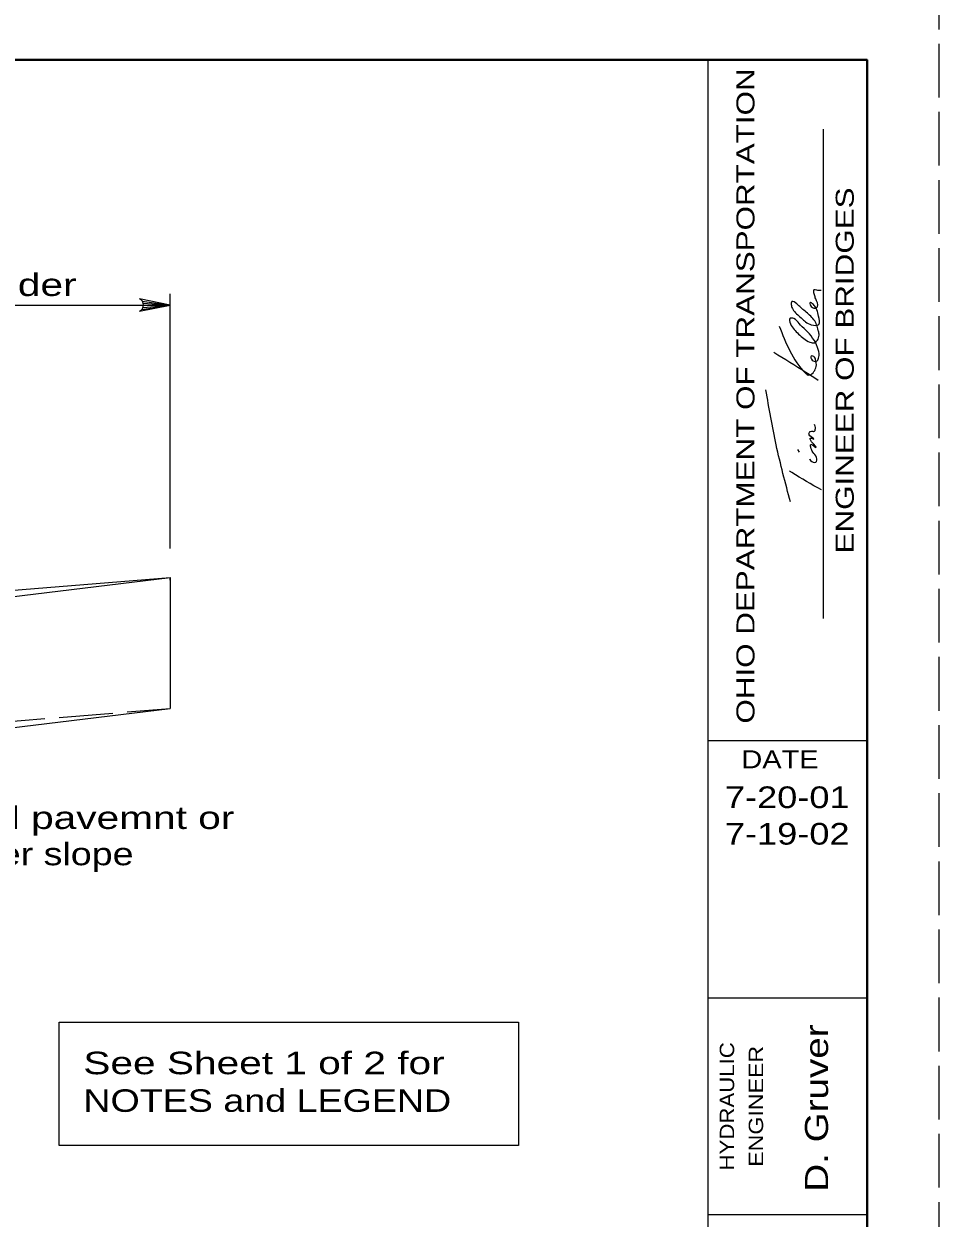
# Model space of a CAD drawing. Extents: x 758.3 to 792.3, y 849.7 to 893.7.
# Drawn here: x 785.98 to 792.32, y 863.16 to 871.44 of the extents above; entities that cross this region are included whole.
import ezdxf
from ezdxf.enums import TextEntityAlignment as Align

# ---------------------------------------------------------------- set-up
doc = ezdxf.new("R2010")
doc.units = 0
doc.header["$LTSCALE"] = 0.062
doc.linetypes.add('LONG_DASHED', pattern=[7.5, 6, -1.5])
doc.layers.add('1', color=7, linetype='Continuous', lineweight=13)

msp = doc.modelspace()

# ---------------------------------------------------------------- linework, layer by layer
at = {"layer": '1', "lineweight": 25}
for p, q in [((760.3205, 871.18817), (791.8205, 871.18817)), ((790.7205, 850.18817), (790.7205, 871.18817)), ((791.8205, 871.18817), (791.8205, 850.18817)), ((781.987, 866.99775), (786.9905, 867.60233)), ((782.38925, 867.23167), (786.9905, 867.60233)), ((786.9905, 867.60233), (786.9905, 866.69533)), ((781.987, 866.09075), (786.9905, 866.69533)), ((791.8205, 866.47233), (790.7205, 866.47233)), ((791.8205, 864.68817), (790.7205, 864.68817)), ((791.8205, 863.18817), (790.7205, 863.18817))]:
    msp.add_line(p, q, dxfattribs=at)
at = {"layer": '1'}
for p, q in [((791.51925, 867.31917), (791.51925, 870.70925)), ((786.9905, 867.80475), (786.9905, 869.56917)), ((781.987, 869.4905), (786.9905, 869.4905)), ((786.79433, 869.4605), (786.9905, 869.4905)), ((786.79667, 869.51758), (786.9905, 869.4905)), ((786.80175, 869.47308), (786.9905, 869.4905)), ((786.80317, 869.50417), (786.9905, 869.4905)), ((786.80517, 869.4905), (786.9905, 869.4905)), ((791.35175, 868.47008), (791.34158, 868.48933)), ((786.9905, 867.58433), (786.9905, 867.60233))]:
    msp.add_line(p, q, dxfattribs=at)
at = {"layer": '1', "linetype": 'LONG_DASHED', "lineweight": 25}
msp.add_line((781.987, 866.29225), (786.9905, 866.69533), dxfattribs=at)
at = {"layer": '1', "linetype": 'LONG_DASHED'}
msp.add_lwpolyline([(758.3205, 849.68817), (792.3205, 849.68817), (792.3205, 871.68817), (758.3205, 871.68817)], close=True, dxfattribs=at)
at = {"layer": '1', "lineweight": 40}
msp.add_lwpolyline([(760.3205, 871.18817), (791.8205, 871.18817), (791.8205, 850.18817), (760.3205, 850.18817)], close=True, dxfattribs=at)
at = {"layer": '1'}
msp.add_lwpolyline([(786.77633, 869.44767), (786.9905, 869.4905), (786.77633, 869.53333)], dxfattribs=at)
at = {"layer": '1', "lineweight": 25}
msp.add_lwpolyline([(786.22108, 864.52333), (789.40483, 864.52333), (789.40483, 863.66692), (786.22108, 863.66692)], close=True, dxfattribs=at)
at = {"layer": '1'}
msp.add_arc((786.75906, 869.49051), 0.04623, 292.08605, 67.91218, dxfattribs=at)
for points in [[(791.21233, 869.34517), (791.3955, 869.01683), (791.41067, 869.00625), (791.42083, 869.00625), (791.45275, 869.02992), (791.46783, 869.06408), (791.46283, 869.11533), (791.44592, 869.13717), (791.43242, 869.13717), (791.43067, 869.12417), (791.44083, 869.109), (791.45433, 869.10058), (791.46942, 869.10058), (791.48458, 869.12217), (791.488, 869.1415), (791.47775, 869.19683), (791.3955, 869.31725), (791.35, 869.36192), (791.31308, 869.3965), (791.28792, 869.39867), (791.28967, 869.36008), (791.31483, 869.32133), (791.38208, 869.259), (791.42417, 869.23358), (791.45783, 869.22908), (791.48117, 869.25508), (791.488, 869.28925), (791.48292, 869.315), (791.45275, 869.38817), (791.4225, 869.42017), (791.36192, 869.47358), (791.33325, 869.49942), (791.29975, 869.51467), (791.29633, 869.48667), (791.30642, 869.46083), (791.36358, 869.40092), (791.43425, 869.35367), (791.48625, 869.356), (791.48458, 869.41367), (791.47275, 869.45658), (791.45942, 869.48233), (791.44925, 869.49308), (791.42583, 869.50808), (791.42758, 869.491), (791.46283, 869.4695), (791.47775, 869.48025), (791.46467, 869.53392), (791.45608, 869.56183), (791.45275, 869.5745), (791.45275, 869.58733), (791.45275, 869.596), (791.47775, 869.59383), (791.50317, 869.59383)], [(791.1735, 869.16292), (791.39725, 869.02542), (791.48292, 868.96975)], [(791.28975, 868.12592), (791.19108, 868.52117), (791.11983, 868.9035)], [(791.42083, 868.42483), (791.42908, 868.41417), (791.46625, 868.40125), (791.471, 868.43367), (791.44592, 868.47008), (791.43067, 868.50633), (791.43067, 868.52558), (791.44592, 868.51933), (791.45608, 868.5085), (791.46625, 868.50417), (791.44258, 868.53633), (791.43067, 868.55133), (791.42758, 868.56867), (791.451, 868.56208), (791.44258, 868.57075), (791.41742, 868.59858), (791.42758, 868.61375), (791.44433, 868.61575), (791.45275, 868.61375), (791.46283, 868.63508), (791.45608, 868.663)], [(791.50492, 868.21033), (791.29975, 868.33033), (791.28417, 868.34075)]]:
    msp.add_spline(points, degree=3, dxfattribs=at)

# ---------------------------------------------------------------- texts
for s, height, width, p in [('OHIO DEPARTMENT OF TRANSPORTATION', 0.125, 1.3, (791.04042, 868.86042)), ('ENGINEER OF BRIDGES', 0.125, 1.3, (791.72875, 869.03721)), ('D. Gruver', 0.16, 1.25, (791.5505, 863.92742)), ('HYDRAULIC', 0.1, 1.15, (790.89958, 863.93925)), ('ENGINEER', 0.1, 1.2, (791.1005, 863.93929))]:
    msp.add_text(s, height=height, rotation=90, dxfattribs=dict(at, width=width)).set_placement(p, align=Align.CENTER)
for s, height, width, p in [('Pavement or Paved shoulder', 0.156, 1.35, (784.525, 869.553)), ('DATE', 0.125, 1.2, (791.21721, 866.28092)), ('7-20-01', 0.15, 1.25, (791.26754, 866.00542)), ('7-19-02', 0.15, 1.25, (791.26754, 865.75233))]:
    msp.add_text(s, height=height, dxfattribs=dict(at, width=width)).set_placement(p, align=Align.CENTER)
for s, width, p in [('Normal pavemnt or', 1.35, (785.03992, 865.86067)), ('shoulder slope', 1.25, (785.03992, 865.6095)), ('See Sheet 1 of 2 for ', 1.35, (786.38775, 864.16167)), ('NOTES and LEGEND', 1.25, (786.38775, 863.901))]:
    msp.add_text(s, height=0.156, dxfattribs=dict(at, width=width)).set_placement(p)

doc.saveas('drawing.dxf')
